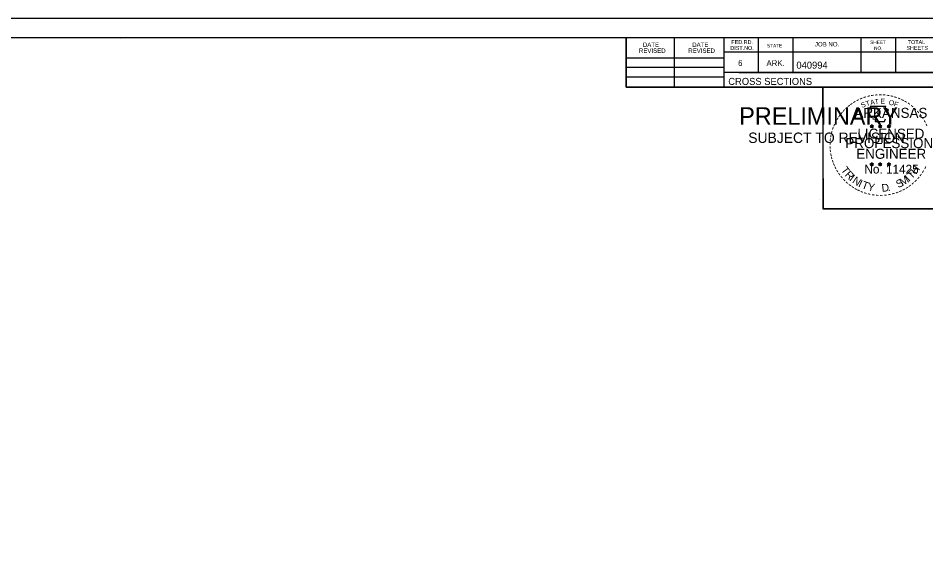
# Model space of a CAD drawing. Extents: x 1381471 to 1382703, y 370300 to 371487.
# Drawn here: x 1382110.7 to 1382292, y 371380.5 to 371487.2 of the extents above; entities that cross this region are included whole.
import ezdxf

# ---------------------------------------------------------------- set-up
doc = ezdxf.new("R2010")
doc.units = 0
doc.layers.add('Level 45', color=7, linetype='Continuous')

msp = doc.modelspace()

# ---------------------------------------------------------------- linework, layer by layer
at = {"layer": 'Level 45'}
for p, q in [((1381966.21, 371487.15), (1382299.55, 371487.15)), ((1381978.61, 371483.26), (1382294.79, 371483.26)), ((1382131.13, 371483), (1382131.13, 371483)), ((1382131.13, 371483), (1382131.13, 371483)), ((1382232.15, 371473.38), (1382232.15, 371483.26)), ((1382241.83, 371473.38), (1382241.83, 371483.26)), ((1382251.69, 371483.26), (1382251.69, 371473.38)), ((1382258.53, 371483.26), (1382258.53, 371476.32)), ((1382265.47, 371483.26), (1382265.47, 371476.32)), ((1382279.05, 371483.26), (1382279.05, 371476.32)), ((1382285.99, 371483.26), (1382285.99, 371476.32)), ((1382232.15, 371479.24), (1382251.69, 371479.24)), ((1382294.79, 371480.32), (1382251.69, 371480.32)), ((1382232.15, 371477.38), (1382251.69, 371477.38)), ((1382232.15, 371475.44), (1382251.69, 371475.44)), ((1382294.79, 371476.32), (1382251.69, 371476.32)), ((1382254.65, 371476.32), (1382294.79, 371476.32)), ((1382294.79, 371473.38), (1382232.15, 371473.38)), ((1382281.23, 371465.89), (1382281.19, 371465.63)), ((1382281.23, 371465.52), (1382281.23, 371465.89)), ((1382281.23, 371465.89), (1382281.28, 371465.64)), ((1382282.9, 371465.89), (1382282.86, 371465.63)), ((1382282.9, 371465.52), (1382282.9, 371465.89)), ((1382282.9, 371465.89), (1382282.95, 371465.64)), ((1382284.66, 371465.87), (1382284.62, 371465.62)), ((1382284.66, 371465.51), (1382284.66, 371465.87)), ((1382284.66, 371465.87), (1382284.71, 371465.62)), ((1382280.88, 371465.63), (1382281.23, 371465.52)), ((1382280.88, 371465.63), (1382281.13, 371465.59)), ((1382280.88, 371465.63), (1382281.12, 371465.51)), ((1382281.01, 371465.22), (1382281.23, 371465.52)), ((1382281.01, 371465.22), (1382281.14, 371465.47)), ((1382281.01, 371465.22), (1382281.23, 371465.44)), ((1382281.57, 371465.63), (1382281.23, 371465.52)), ((1382281.44, 371465.22), (1382281.23, 371465.52)), ((1382281.44, 371465.22), (1382281.23, 371465.44)), ((1382281.57, 371465.63), (1382281.29, 371465.58)), ((1382281.44, 371465.22), (1382281.3, 371465.51)), ((1382281.57, 371465.63), (1382281.37, 371465.53)), ((1382282.55, 371465.63), (1382282.9, 371465.52)), ((1382282.55, 371465.63), (1382282.8, 371465.59)), ((1382282.55, 371465.63), (1382282.79, 371465.51)), ((1382282.68, 371465.22), (1382282.9, 371465.52)), ((1382282.68, 371465.22), (1382282.81, 371465.47)), ((1382282.68, 371465.22), (1382282.9, 371465.44)), ((1382283.24, 371465.63), (1382282.9, 371465.52)), ((1382283.11, 371465.22), (1382282.9, 371465.52)), ((1382283.11, 371465.22), (1382282.9, 371465.44)), ((1382283.24, 371465.63), (1382282.96, 371465.58)), ((1382283.11, 371465.22), (1382282.97, 371465.51)), ((1382283.24, 371465.63), (1382283.04, 371465.53)), ((1382284.31, 371465.62), (1382284.66, 371465.51)), ((1382284.31, 371465.62), (1382284.57, 371465.57)), ((1382284.31, 371465.62), (1382284.55, 371465.5)), ((1382284.45, 371465.21), (1382284.66, 371465.51)), ((1382284.45, 371465.21), (1382284.57, 371465.46)), ((1382284.45, 371465.21), (1382284.66, 371465.43)), ((1382285.01, 371465.62), (1382284.66, 371465.51)), ((1382284.87, 371465.21), (1382284.66, 371465.51)), ((1382284.87, 371465.21), (1382284.66, 371465.43)), ((1382285.01, 371465.62), (1382284.72, 371465.57)), ((1382284.87, 371465.21), (1382284.74, 371465.5)), ((1382285.01, 371465.62), (1382284.8, 371465.52)), ((1382280.87, 371458.06), (1382281.22, 371457.95)), ((1382280.87, 371458.06), (1382281.13, 371458.01)), ((1382280.87, 371458.06), (1382281.11, 371457.94)), ((1382281.01, 371457.65), (1382281.22, 371457.95)), ((1382281.01, 371457.65), (1382281.13, 371457.89)), ((1382281.01, 371457.65), (1382281.22, 371457.87)), ((1382281.22, 371458.31), (1382281.18, 371458.06)), ((1382281.22, 371457.95), (1382281.22, 371458.31)), ((1382281.22, 371458.31), (1382281.27, 371458.06)), ((1382281.57, 371458.06), (1382281.22, 371457.95)), ((1382281.44, 371457.65), (1382281.22, 371457.95)), ((1382281.44, 371457.65), (1382281.22, 371457.86)), ((1382281.57, 371458.06), (1382281.28, 371458.01)), ((1382281.44, 371457.65), (1382281.3, 371457.94)), ((1382281.57, 371458.06), (1382281.37, 371457.96)), ((1382282.54, 371458.06), (1382282.89, 371457.95)), ((1382282.54, 371458.06), (1382282.8, 371458.01)), ((1382282.54, 371458.06), (1382282.78, 371457.94)), ((1382282.68, 371457.65), (1382282.89, 371457.95)), ((1382282.68, 371457.65), (1382282.8, 371457.89)), ((1382282.68, 371457.65), (1382282.89, 371457.87)), ((1382282.89, 371458.31), (1382282.85, 371458.06)), ((1382282.89, 371457.95), (1382282.89, 371458.31)), ((1382282.89, 371458.31), (1382282.94, 371458.06)), ((1382283.24, 371458.06), (1382282.89, 371457.95)), ((1382283.11, 371457.65), (1382282.89, 371457.95)), ((1382283.11, 371457.65), (1382282.89, 371457.86)), ((1382283.24, 371458.06), (1382282.95, 371458.01)), ((1382283.11, 371457.65), (1382282.97, 371457.94)), ((1382283.24, 371458.06), (1382283.04, 371457.96)), ((1382284.31, 371458.05), (1382284.66, 371457.94)), ((1382284.31, 371458.05), (1382284.56, 371458)), ((1382284.31, 371458.05), (1382284.55, 371457.93)), ((1382284.44, 371457.64), (1382284.66, 371457.94)), ((1382284.44, 371457.64), (1382284.57, 371457.88)), ((1382284.44, 371457.64), (1382284.66, 371457.86)), ((1382284.66, 371458.3), (1382284.62, 371458.05)), ((1382284.66, 371457.94), (1382284.66, 371458.3)), ((1382284.66, 371458.3), (1382284.71, 371458.05)), ((1382285.01, 371458.05), (1382284.66, 371457.94)), ((1382284.87, 371457.64), (1382284.66, 371457.94)), ((1382284.87, 371457.64), (1382284.66, 371457.85)), ((1382285.01, 371458.05), (1382284.72, 371458)), ((1382284.87, 371457.64), (1382284.74, 371457.93)), ((1382285.01, 371458.05), (1382284.8, 371457.95)), ((1382270.83, 371450.92), (1382270.83, 371450.92))]:
    msp.add_line(p, q, dxfattribs=at)
for points in [[(1381966.21, 371487.15), (1382299.55, 371487.15), (1382299.55, 371273.81), (1381966.21, 371273.81)], [(1382212.53, 371483.26), (1382232.15, 371483.26), (1382232.15, 371473.38), (1382248.27, 371473.38), (1382271.46, 371473.38), (1382271.46, 371449.04), (1382294.79, 371449.04), (1382294.79, 371277.8), (1381978.61, 371277.8), (1381978.61, 371483.26)], [(1382271.46, 371473.38), (1382294.67, 371473.38), (1382294.79, 371449.04), (1382271.59, 371449.04)]]:
    msp.add_lwpolyline(points, close=True, dxfattribs=at)
for points in [[(1382280.92, 371469.51), (1382281.19, 371468.68)], [(1382284.43, 371468.59), (1382284.57, 371468.87), (1382283.89, 371468.85), (1382284.04, 371469.51), (1382280.92, 371469.51)], [(1382281.23, 371465.89), (1382281.44, 371465.22), (1382280.88, 371465.63), (1382281.57, 371465.63), (1382281.01, 371465.22), (1382281.23, 371465.89)], [(1382281.41, 371467.09), (1382281.41, 371467), (1382281.97, 371466.98), (1382281.92, 371466.51), (1382283.79, 371466.51), (1382283.99, 371467.04)], [(1382282.9, 371465.89), (1382283.11, 371465.22), (1382282.55, 371465.63), (1382283.24, 371465.63), (1382282.68, 371465.22), (1382282.9, 371465.89)], [(1382284.66, 371465.87), (1382284.87, 371465.21), (1382284.31, 371465.62), (1382285.01, 371465.62), (1382284.45, 371465.21), (1382284.66, 371465.87)], [(1382281.22, 371458.31), (1382281.44, 371457.65), (1382280.87, 371458.06), (1382281.57, 371458.06), (1382281.01, 371457.65), (1382281.22, 371458.31)], [(1382282.89, 371458.31), (1382283.11, 371457.65), (1382282.54, 371458.06), (1382283.24, 371458.06), (1382282.68, 371457.65), (1382282.89, 371458.31)], [(1382284.66, 371458.3), (1382284.87, 371457.64), (1382284.31, 371458.05), (1382285.01, 371458.05), (1382284.44, 371457.64), (1382284.66, 371458.3)]]:
    msp.add_lwpolyline(points, dxfattribs=at)
for centre, radius in [((1382281.23, 371465.52), 0.172), ((1382281.23, 371465.52), 0.145), ((1382281.23, 371465.52), 0.116), ((1382281.23, 371465.52), 0.0991), ((1382281.23, 371465.52), 0.0747), ((1382281.23, 371465.52), 0.0495), ((1382281.23, 371465.52), 0.0296), ((1382282.9, 371465.52), 0.172), ((1382282.9, 371465.52), 0.145), ((1382282.9, 371465.52), 0.116), ((1382282.9, 371465.52), 0.0991), ((1382282.9, 371465.52), 0.0747), ((1382282.9, 371465.52), 0.0495), ((1382282.9, 371465.52), 0.0296), ((1382284.66, 371465.51), 0.172), ((1382284.66, 371465.51), 0.145), ((1382284.66, 371465.51), 0.116), ((1382284.66, 371465.51), 0.0991), ((1382284.66, 371465.51), 0.0747), ((1382284.66, 371465.51), 0.0495), ((1382284.66, 371465.51), 0.0296), ((1382281.22, 371457.95), 0.172), ((1382281.22, 371457.95), 0.145), ((1382281.22, 371457.95), 0.116), ((1382281.22, 371457.95), 0.0991), ((1382281.22, 371457.95), 0.0747), ((1382281.22, 371457.95), 0.0495), ((1382281.22, 371457.95), 0.0296), ((1382282.89, 371457.95), 0.172), ((1382282.89, 371457.95), 0.145), ((1382282.89, 371457.95), 0.116), ((1382282.89, 371457.95), 0.0991), ((1382282.89, 371457.95), 0.0747), ((1382282.89, 371457.95), 0.0495), ((1382282.89, 371457.95), 0.0296), ((1382284.66, 371457.94), 0.172), ((1382284.66, 371457.94), 0.145), ((1382284.66, 371457.94), 0.116), ((1382284.66, 371457.94), 0.0991), ((1382284.66, 371457.94), 0.0747), ((1382284.66, 371457.94), 0.0495), ((1382284.66, 371457.94), 0.0296)]:
    msp.add_circle(centre, radius, dxfattribs=at)

# ---------------------------------------------------------------- texts
for s, height, rotation, p in [('DATE', 0.879, 360, (1382235.49, 371481.39)), ('DATE', 0.879, 360, (1382245.35, 371481.39)), ('FED.RD.', 0.782, 360, (1382253.17, 371481.98)), ('JOB NO.', 0.879, 360, (1382269.87, 371481.5)), ('SHEET', 0.684, 360, (1382280.91, 371481.98)), ('TOTAL', 0.782, 360, (1382288.43, 371481.98)), ('REVISED', 0.879, 360, (1382234.71, 371480.21)), ('REVISED', 0.879, 360, (1382244.57, 371480.21)), ('DIST.NO.', 0.782, 360, (1382252.97, 371480.8)), ('STATE', 0.684, 360, (1382260.29, 371481.3)), ('NO.', 0.684, 360, (1382281.69, 371480.8)), ('SHEETS', 0.782, 360, (1382288.15, 371480.8)), ('6', 1.17, 360, (1382254.53, 371477.58)), ('ARK.', 1.172, 360, (1382260.19, 371477.58)), ('040994', 1.4, 360, (1382266.17, 371477.06)), ('CROSS SECTIONS', 1.4, 360, (1382252.56, 371473.81)), ('-', 1.6, 19.1761, (1382279.67, 371470.64)), ('-', 1.6, 13.6301, (1382280.42, 371470.88)), ('-', 1.6, 10.2193, (1382281.1, 371471.04)), ('-', 1.6, 5.8968, (1382281.82, 371471.15)), ('-', 1.6, 0.1862, (1382282.6, 371471.22)), ('-', 1.6, 357.743, (1382283.32, 371471.21)), ('-', 1.6, 352.1617, (1382284.06, 371471.15)), ('-', 1.6, 347.2049, (1382284.78, 371471.04)), ('-', 1.6, 342.3362, (1382285.42, 371470.88)), ('-', 1.6, 38.9507, (1382276.75, 371468.91)), ('-', 1.6, 36.2317, (1382277.23, 371469.29)), ('-', 1.6, 34.0636, (1382277.8, 371469.68)), ('-', 1.6, 28.7918, (1382278.4, 371470.05)), ('-', 1.6, 24.3072, (1382279.03, 371470.37)), ('S', 1, 21.594, (1382279.27, 371469.19)), ('T', 1, 16.4036, (1382280.19, 371469.52)), ('A', 1, 11.2132, (1382281.01, 371469.77)), ('T', 1, 6.0228, (1382281.86, 371469.94)), ('E', 1, 0.8323, (1382282.97, 371470.05)), ('O', 1, 350.4515, (1382284.57, 371469.84)), ('F', 1, 340.0707, (1382285.53, 371469.61)), ('-', 1.6, 337.8551, (1382286.15, 371470.66)), ('-', 1.6, 334.1211, (1382286.78, 371470.39)), ('-', 1.6, 329.6409, (1382287.36, 371470.11)), ('-', 1.6, 325.8627, (1382288.01, 371469.75)), ('-', 1.6, 320.5297, (1382288.62, 371469.32)), ('PRELIMINARY', 3.5, 360, (1382254.74, 371465.84)), ('DWB', 0.01, 360, (1382255.49, 371467.69)), ('-', 1.6, 54.2325, (1382275.05, 371466.96)), ('-', 1.6, 50.6142, (1382275.47, 371467.53)), ('-', 1.6, 48.423, (1382275.87, 371468.01)), ('-', 1.6, 42.9622, (1382276.32, 371468.49)), ('ARKANSAS', 2, 360, (1382277.77, 371467.22)), ('-', 1.6, 315.5786, (1382289.21, 371468.83)), ('-', 1.6, 309.8797, (1382289.78, 371468.28)), ('-', 1.6, 306.6522, (1382290.31, 371467.68)), ('-', 1.6, 67.7743, (1382274.16, 371465.21)), ('-', 1.6, 62.8713, (1382274.41, 371465.82)), ('-', 1.6, 58.0706, (1382274.73, 371466.43)), ('-', 1.4, 303.6753, (1382290.79, 371467.11)), ('-', 1.6, 299.6684, (1382291.11, 371466.5)), ('-', 1.6, 294.6628, (1382291.44, 371465.89)), ('SUBJECT TO REVISION', 2.0751, 360, (1382256.55, 371462.21)), ('-', 1.6, 75.461, (1382273.74, 371463.86)), ('-', 1.6, 72.3945, (1382273.94, 371464.58)), ('LICENSED', 2, 360, (1382278.37, 371463.07)), ('DWB', 0.01, 360, (1382281.21, 371465.52)), ('DWB', 0.01, 360, (1382282.88, 371465.52)), ('DWB', 0.01, 360, (1382284.65, 371465.5)), ('-', 1.6, 89.0622, (1382273.51, 371461.76)), ('-', 1.6, 85.1863, (1382273.53, 371462.46)), ('-', 1.6, 81.2013, (1382273.61, 371463.15)), ('PROFESSIONAL', 2, 360, (1382275.95, 371461.17)), ('-', 1.6, 94.1959, (1382273.54, 371461.03)), ('-', 1.6, 98.9479, (1382273.61, 371460.37)), ('ENGINEER', 2, 360, (1382278.13, 371459.04)), ('-', 1.6, 101.7149, (1382273.75, 371459.63)), ('-', 1.6, 105.4578, (1382273.91, 371459.04)), ('-', 1.6, 109.0874, (1382274.13, 371458.41)), ('-', 1.6, 114.0643, (1382274.38, 371457.81)), ('-', 1.6, 115.7289, (1382274.68, 371457.19)), ('-', 1.6, 120.4471, (1382275.04, 371456.61)), ('T', 1.54, 306.0406, (1382274.98, 371456.79)), ('No. 11425', 1.757, 360, (1382279.76, 371456.09)), ('DWB', 0.01, 360, (1382281.21, 371457.94)), ('DWB', 0.01, 360, (1382282.88, 371457.94)), ('DWB', 0.01, 360, (1382284.65, 371457.93)), ('T', 1.54, 46.6444, (1382289.21, 371454.88)), ('H', 1.54, 54.6088, (1382290.1, 371455.82)), ('-', 1.6, 244.6197, (1382291.52, 371457.85)), ('-', 1.6, 125.8934, (1382275.44, 371456.05)), ('-', 1.6, 130.7181, (1382275.91, 371455.49)), ('-', 1.6, 134.2238, (1382276.42, 371454.95)), ('R', 1.54, 314.005, (1382275.75, 371455.74)), ('I', 1.54, 321.9694, (1382276.65, 371454.81)), ('N', 1.54, 326.5002, (1382277.21, 371454.33)), ('M', 1.54, 32.6563, (1382287.37, 371453.55)), ('I', 1.54, 42.1136, (1382288.65, 371454.4)), ('-', 1.6, 231.2538, (1382290.29, 371455.88)), ('-', 1.6, 233.8452, (1382290.72, 371456.45)), ('-', 1.6, 239.0712, (1382291.12, 371457.1)), ('-', 1.6, 138.9338, (1382276.95, 371454.49)), ('-', 1.6, 144.6463, (1382277.5, 371454.08)), ('-', 1.6, 148.0898, (1382278.07, 371453.71)), ('-', 1.6, 151.5704, (1382278.64, 371453.38)), ('I', 1.54, 335.3603, (1382278.42, 371453.55)), ('T', 1.54, 339.8912, (1382279.08, 371453.22)), ('Y', 1.54, 347.8556, (1382280.3, 371452.78)), ('D', 1.54, 6.3969, (1382283.28, 371452.42)), ('S', 1.54, 26.9312, (1382286.53, 371453.15)), ('-', 1.6, 212.2491, (1382288.21, 371453.95)), ('-', 1.6, 215.7363, (1382288.74, 371454.34)), ('-', 1.6, 221.0851, (1382289.29, 371454.81)), ('-', 1.6, 225.7653, (1382289.81, 371455.32)), ('-', 1.6, 154.6002, (1382279.17, 371453.14)), ('-', 1.6, 158.5612, (1382279.79, 371452.88)), ('-', 1.6, 162.7983, (1382280.48, 371452.67)), ('-', 1.6, 167.5555, (1382281.19, 371452.51)), ('-', 1.6, 173.1155, (1382281.96, 371452.4)), ('-', 1.6, 176.5183, (1382282.71, 371452.34)), ('-', 1.6, 181.5918, (1382283.46, 371452.36)), ('-', 1.6, 185.8167, (1382284.27, 371452.44)), ('-', 1.6, 191.2858, (1382285, 371452.57)), ('.', 1.54, 13.7642, (1382284.48, 371452.54)), ('-', 1.6, 195.4743, (1382285.73, 371452.77)), ('-', 1.6, 200.7184, (1382286.41, 371453.01)), ('-', 1.6, 204.2516, (1382287.03, 371453.28)), ('-', 1.6, 207.3568, (1382287.65, 371453.6))]:
    msp.add_text(s, height=height, rotation=rotation, dxfattribs=at).set_placement(p)

doc.saveas('drawing.dxf')
